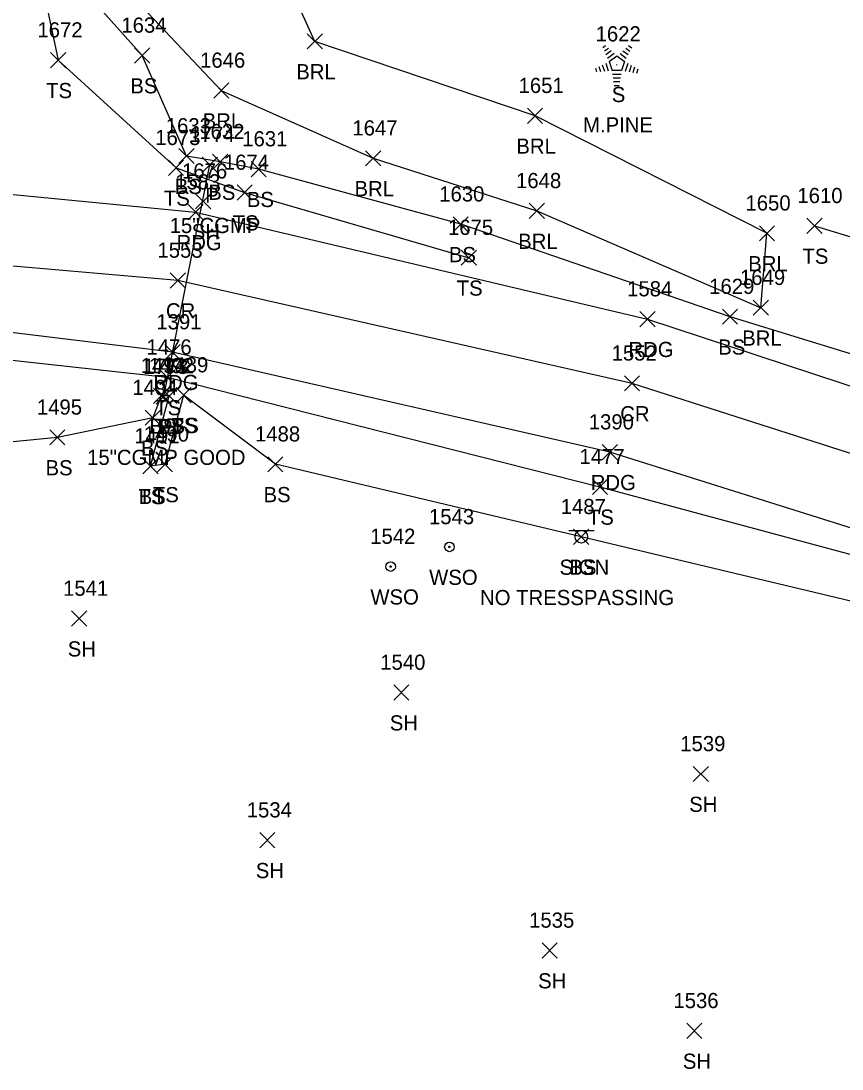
# Model space of a CAD drawing. Extents: x 1609623 to 1616187, y 756677 to 762826.
# Drawn here: x 1610314.5 to 1610422.7, y 761639.6 to 761777.7 of the extents above; entities that cross this region are included whole.
import ezdxf

# ---------------------------------------------------------------- set-up
doc = ezdxf.new("R2010")
doc.units = 0
for name, color, linetype in [('D_A', 7, 'Continuous'), ('D_C', 7, 'Continuous'), ('D_I', 7, 'Continuous'), ('D_TIC', 7, 'Continuous'), ('DCP', 7, 'Continuous'), ('L_A', 7, 'Continuous'), ('L_C', 7, 'Continuous'), ('L_I', 7, 'Continuous'), ('L_TIC', 7, 'Continuous'), ('LABL', 7, 'Continuous'), ('LELB', 7, 'Continuous'), ('LTC', 7, 'Continuous'), ('P_A', 7, 'Continuous'), ('P_I', 7, 'Continuous'), ('P_TIC', 7, 'Continuous'), ('PEU', 7, 'Continuous'), ('PRC', 7, 'Continuous'), ('S_A', 7, 'Continuous'), ('S_C', 7, 'Continuous'), ('S_I', 7, 'Continuous'), ('SSGN', 7, 'Continuous'), ('U_A', 7, 'Continuous'), ('U_I', 7, 'Continuous'), ('UWV', 7, 'Continuous')]:
    doc.layers.add(name, color=color, linetype=linetype)

msp = doc.modelspace()

# ---------------------------------------------------------------- linework, layer by layer
at = {"layer": 'D_TIC'}
for points in [[(1610338.4, 761757.75), (1610340.4, 761759.75)], [(1610340.4, 761757.75), (1610338.4, 761759.75)], [(1610332.32, 761727.19), (1610334.32, 761729.19)], [(1610334.32, 761727.19), (1610332.32, 761729.19)]]:
    msp.add_lwpolyline(points, dxfattribs=at)
at = {"layer": 'DCP'}
msp.add_lwpolyline([(1610333.32, 761728.19), (1610339.4, 761758.75)], dxfattribs=at)
at = {"layer": 'L_TIC'}
for points in [[(1610352.23, 761774.02), (1610354.23, 761776.02)], [(1610354.23, 761774.02), (1610352.23, 761776.02)], [(1610318.42, 761771.53), (1610320.42, 761773.53)], [(1610320.42, 761771.53), (1610318.42, 761773.53)], [(1610329.48, 761772.16), (1610331.48, 761774.16)], [(1610331.48, 761772.16), (1610329.48, 761774.16)], [(1610339.9, 761767.54), (1610341.9, 761769.54)], [(1610341.9, 761767.54), (1610339.9, 761769.54)], [(1610381.23, 761764.21), (1610383.23, 761766.21)], [(1610383.23, 761764.21), (1610381.23, 761766.21)], [(1610335.33, 761758.9), (1610337.33, 761760.9)], [(1610337.33, 761758.9), (1610335.33, 761760.9)], [(1610359.91, 761758.61), (1610361.91, 761760.61)], [(1610361.91, 761758.61), (1610359.91, 761760.61)], [(1610333.94, 761757.35), (1610335.94, 761759.35)], [(1610335.94, 761757.35), (1610333.94, 761759.35)], [(1610339.75, 761758.13), (1610341.75, 761760.13)], [(1610341.75, 761758.13), (1610339.75, 761760.13)], [(1610344.83, 761757.18), (1610346.83, 761759.18)], [(1610346.83, 761757.18), (1610344.83, 761759.18)], [(1610342.98, 761754.09), (1610344.98, 761756.09)], [(1610344.98, 761754.09), (1610342.98, 761756.09)], [(1610337.52, 761752.94), (1610339.52, 761754.94)], [(1610339.52, 761752.94), (1610337.52, 761754.94)], [(1610381.47, 761751.67), (1610383.47, 761753.67)], [(1610383.47, 761751.67), (1610381.47, 761753.67)], [(1610371.44, 761749.91), (1610373.44, 761751.91)], [(1610373.44, 761749.91), (1610371.44, 761751.91)], [(1610418.05, 761749.7), (1610420.05, 761751.7)], [(1610420.05, 761749.7), (1610418.05, 761751.7)], [(1610411.78, 761748.72), (1610413.78, 761750.72)], [(1610413.78, 761748.72), (1610411.78, 761750.72)], [(1610372.5, 761745.5), (1610374.5, 761747.5)], [(1610374.5, 761745.5), (1610372.5, 761747.5)], [(1610410.98, 761738.91), (1610412.98, 761740.91)], [(1610412.98, 761738.91), (1610410.98, 761740.91)], [(1610406.92, 761737.73), (1610408.92, 761739.73)], [(1610408.92, 761737.73), (1610406.92, 761739.73)], [(1610332.79, 761729.74), (1610334.79, 761731.74)], [(1610334.79, 761729.74), (1610332.79, 761731.74)], [(1610331.98, 761727.3), (1610333.98, 761729.3)], [(1610333.98, 761727.3), (1610331.98, 761729.3)], [(1610333.04, 761727.28), (1610335.04, 761729.28)], [(1610335.04, 761727.28), (1610333.04, 761729.28)], [(1610334.94, 761727.39), (1610336.94, 761729.39)], [(1610336.94, 761727.39), (1610334.94, 761729.39)], [(1610334.94, 761727.39), (1610336.94, 761729.39)], [(1610336.94, 761727.39), (1610334.94, 761729.39)], [(1610330.88, 761724.41), (1610332.88, 761726.41)], [(1610332.88, 761724.41), (1610330.88, 761726.41)], [(1610318.31, 761721.82), (1610320.31, 761723.82)], [(1610320.31, 761721.82), (1610318.31, 761723.82)], [(1610330.58, 761718.03), (1610332.58, 761720.03)], [(1610332.58, 761718.03), (1610330.58, 761720.03)], [(1610330.58, 761718.03), (1610332.58, 761720.03)], [(1610332.58, 761718.03), (1610330.58, 761720.03)], [(1610332.48, 761718.27), (1610334.48, 761720.27)], [(1610334.48, 761718.27), (1610332.48, 761720.27)], [(1610347.03, 761718.28), (1610349.03, 761720.28)], [(1610349.03, 761718.28), (1610347.03, 761720.28)], [(1610389.78, 761715.31), (1610391.78, 761717.31)], [(1610391.78, 761715.31), (1610389.78, 761717.31)], [(1610387.31, 761708.71), (1610389.31, 761710.71)], [(1610389.31, 761708.71), (1610387.31, 761710.71)], [(1610321.19, 761697.94), (1610323.19, 761699.94)], [(1610323.19, 761697.94), (1610321.19, 761699.94)], [(1610363.62, 761688.19), (1610365.62, 761690.19)], [(1610365.62, 761688.19), (1610363.62, 761690.19)], [(1610403.06, 761677.46), (1610405.06, 761679.46)], [(1610405.06, 761677.46), (1610403.06, 761679.46)], [(1610345.96, 761668.73), (1610347.96, 761670.73)], [(1610347.96, 761668.73), (1610345.96, 761670.73)], [(1610383.15, 761654.2), (1610385.15, 761656.2)], [(1610385.15, 761654.2), (1610383.15, 761656.2)], [(1610402.21, 761643.6), (1610404.21, 761645.6)], [(1610404.21, 761643.6), (1610402.21, 761645.6)]]:
    msp.add_lwpolyline(points, dxfattribs=at)
at = {"layer": 'LABL'}
msp.add_lwpolyline([(1610330.75, 761800.05), (1610325.36, 761785.05), (1610340.9, 761768.54), (1610360.91, 761759.61), (1610382.47, 761752.67), (1610411.98, 761739.91), (1610412.78, 761749.72), (1610382.23, 761765.21), (1610353.23, 761775.02), (1610345.84, 761791.3)], dxfattribs=at)
at = {"layer": 'LELB'}
for points in [[(1610357.94, 761824.49), (1610329.65, 761813.17), (1610320.02, 761813.81), (1610314.97, 761798.32), (1610316.77, 761785.03), (1610319.42, 761772.53), (1610334.94, 761758.35), (1610343.98, 761755.09), (1610373.5, 761746.5)], [(1610493.54, 761807.83), (1610484.15, 761757.42), (1610484.55, 761721.1), (1610476.31, 761717.56), (1610462.82, 761719), (1610432.23, 761731.26), (1610407.92, 761738.73), (1610372.44, 761750.91), (1610345.83, 761758.18), (1610340.75, 761759.13), (1610336.33, 761759.9), (1610330.48, 761773.16), (1610321.56, 761783.18), (1610327.07, 761799.85), (1610336.71, 761810.65), (1610352.98, 761818.88), (1610362.46, 761822.54)], [(1610419.05, 761750.7), (1610448.86, 761741.64), (1610467.36, 761735.16), (1610472.33, 761756.91), (1610479.31, 761783.98), (1610481.94, 761811.25), (1610453.47, 761810.17), (1610420.45, 761799.24), (1610406.2, 761793.3), (1610384.28, 761797.2), (1610367.96, 761799.15), (1610357.1, 761783.9)], [(1610257.48, 761736.51), (1610289.65, 761735.58), (1610333.79, 761730.74), (1610390.78, 761716.31), (1610438.56, 761703.45), (1610479.41, 761687.45), (1610522.96, 761672.19), (1610559.63, 761661.11), (1610576.64, 761653.22)], [(1610331.58, 761719.03), (1610334.04, 761728.28), (1610332.98, 761728.3), (1610331.88, 761725.41), (1610319.31, 761722.82), (1610270.59, 761718.07), (1610241.74, 761657.34), (1610217.07, 761660.78), (1610191.82, 761655.02), (1610167.15, 761677.06), (1610169.37, 761706.02), (1610154.67, 761706.22), (1610148.61, 761677.65)], [(1610335.94, 761728.39), (1610333.48, 761719.27), (1610331.58, 761719.03)], [(1610558.74, 761658.14), (1610522.76, 761668.49), (1610478.5, 761684.35), (1610437.45, 761698), (1610388.31, 761709.71), (1610348.03, 761719.28), (1610335.94, 761728.39)]]:
    msp.add_lwpolyline(points, dxfattribs=at)
at = {"layer": 'LTC'}
for p, q in [((1610391.15, 761774.22), (1610391.5, 761774.47)), ((1610394.55, 761774.46), (1610394.97, 761774.15)), ((1610391.36, 761773.75), (1610391.89, 761774.13)), ((1610391.57, 761773.28), (1610392.27, 761773.8)), ((1610391.78, 761772.82), (1610392.66, 761773.46)), ((1610392, 761772.36), (1610393.01, 761773.1)), ((1610393.01, 761773.1), (1610394.01, 761772.37)), ((1610393.43, 761773.41), (1610394.24, 761772.82)), ((1610393.81, 761773.76), (1610394.48, 761773.27)), ((1610394.18, 761774.11), (1610394.73, 761773.71)), ((1610390.64, 761771.71), (1610390.85, 761771.06)), ((1610391.09, 761771.93), (1610391.36, 761771.09)), ((1610391.55, 761772.14), (1610391.88, 761771.13)), ((1610392, 761772.36), (1610392.39, 761771.17)), ((1610394.01, 761772.37), (1610393.62, 761771.17)), ((1610394.45, 761772.1), (1610394.11, 761771.06)), ((1610394.89, 761771.85), (1610394.61, 761770.97)), ((1610395.34, 761771.6), (1610395.1, 761770.87)), ((1610390.18, 761771.49), (1610390.33, 761771.03)), ((1610393.62, 761771.17), (1610392.39, 761771.17)), ((1610393.58, 761770.67), (1610392.44, 761770.67)), ((1610395.78, 761771.35), (1610395.6, 761770.78)), ((1610393.5, 761770.17), (1610392.51, 761770.17)), ((1610393.41, 761769.67), (1610392.58, 761769.67)), ((1610393.33, 761769.17), (1610392.66, 761769.17))]:
    msp.add_line(p, q, dxfattribs=at)
at = {"layer": 'P_TIC'}
for points in [[(1610336.52, 761751.5), (1610338.52, 761753.5)], [(1610338.52, 761751.5), (1610336.52, 761753.5)], [(1610334.18, 761742.5), (1610336.18, 761744.5)], [(1610336.18, 761742.5), (1610334.18, 761744.5)], [(1610396.05, 761737.41), (1610398.05, 761739.41)], [(1610398.05, 761737.41), (1610396.05, 761739.41)], [(1610333.48, 761733.06), (1610335.48, 761735.06)], [(1610335.48, 761733.06), (1610333.48, 761735.06)], [(1610394.01, 761728.94), (1610396.01, 761730.94)], [(1610396.01, 761728.94), (1610394.01, 761730.94)], [(1610391.08, 761719.87), (1610393.08, 761721.87)], [(1610393.08, 761719.87), (1610391.08, 761721.87)]]:
    msp.add_lwpolyline(points, dxfattribs=at)
at = {"layer": 'PEU'}
for points in [[(1610292.65, 761756.84), (1610337.52, 761752.5), (1610397.05, 761738.41), (1610444.38, 761722.79), (1610486.74, 761705.69), (1610529.9, 761690.62)], [(1610523.28, 761673.99), (1610480.04, 761689.74), (1610439, 761706.13), (1610392.08, 761720.87), (1610334.48, 761734.06), (1610288.63, 761739.63), (1610237.75, 761740.33), (1610189.36, 761741.54), (1610151.21, 761743.29), (1610095.63, 761747.13), (1610049.42, 761749.13), (1609994.68, 761742.82), (1609943, 761732.03), (1609889.61, 761718.43), (1609806.51, 761697.21)]]:
    msp.add_lwpolyline(points, dxfattribs=at)
at = {"layer": 'PRC'}
msp.add_lwpolyline([(1610601.8, 761670.75), (1610582.15, 761672.46), (1610527.05, 761683.5), (1610483.24, 761698.98), (1610440.53, 761715.33), (1610395.01, 761729.94), (1610335.18, 761743.5), (1610288.69, 761747.54), (1610237.99, 761746.29), (1610189.61, 761747.71), (1610150.7, 761750.53), (1610096.59, 761755.33), (1610048.73, 761756.09), (1609993.41, 761750.2), (1609941.26, 761738.94), (1609887.62, 761725.82), (1609805.01, 761705.08)], dxfattribs=at)
at = {"layer": 'SSGN'}
for p, q in [((1610386.68, 761710.56), (1610390.01, 761710.56)), ((1610388.33, 761709.73), (1610388.33, 761709.73))]:
    msp.add_line(p, q, dxfattribs=at)
msp.add_circle((1610388.33, 761709.73), 0.833, dxfattribs=at)
at = {"layer": 'UWV'}
for centre, radius in [((1610370.95, 761708.38), 0.625), ((1610370.95, 761708.38), 0.0833), ((1610363.21, 761705.79), 0.625), ((1610363.21, 761705.79), 0.0833)]:
    msp.add_circle(centre, radius, dxfattribs=at)

# ---------------------------------------------------------------- texts
at = {"layer": 'D_A'}
for p in [(1610338.78, 761753.75), (1610332.69, 761723.19)]:
    msp.add_text('P', height=2, dxfattribs=at).set_placement(p)
at = {"layer": 'D_C'}
for s, p in [('15"CGMP', (1610334.1, 761749.75)), ('15"CGMP GOOD', (1610323.23, 761719.19))]:
    msp.add_text(s, height=2, dxfattribs=at).set_placement(p)
at = {"layer": 'D_I'}
for s, p in [('1774', (1610336.71, 761761.75)), ('1773', (1610330.62, 761731.19))]:
    msp.add_text(s, height=2, dxfattribs=at).set_placement(p)
at = {"layer": 'L_A'}
for s, p in [('BRL', (1610350.78, 761770.02)), ('TS', (1610317.83, 761767.53)), ('BS', (1610328.92, 761768.16)), ('S', (1610392.34, 761767.01)), ('BRL', (1610338.45, 761763.54)), ('BRL', (1610379.77, 761760.21)), ('BS', (1610334.77, 761754.9)), ('BRL', (1610358.45, 761754.61)), ('TS', (1610333.34, 761753.35)), ('BS', (1610339.19, 761754.13)), ('BS', (1610344.27, 761753.18)), ('SH', (1610337.01, 761748.94)), ('TS', (1610342.39, 761750.09)), ('BRL', (1610380.01, 761747.67)), ('BS', (1610370.88, 761745.91)), ('BRL', (1610410.32, 761744.72)), ('TS', (1610417.46, 761745.7)), ('TS', (1610371.91, 761741.5)), ('BS', (1610406.36, 761733.73)), ('BRL', (1610409.52, 761734.91)), ('TS', (1610332.2, 761725.74)), ('BS', (1610331.42, 761723.3)), ('BS', (1610332.48, 761723.28)), ('TS', (1610334.35, 761723.39)), ('BS', (1610334.38, 761723.39)), ('BS', (1610330.32, 761720.41)), ('BS', (1610317.75, 761717.82)), ('TS', (1610329.99, 761714.03)), ('BS', (1610330.02, 761714.03)), ('TS', (1610331.89, 761714.27)), ('BS', (1610346.47, 761714.28)), ('TS', (1610389.19, 761711.31)), ('BS', (1610386.75, 761704.71)), ('SH', (1610320.68, 761693.94)), ('SH', (1610363.1, 761684.19)), ('SH', (1610402.54, 761673.46)), ('SH', (1610345.45, 761664.73)), ('SH', (1610382.64, 761650.2)), ('SH', (1610401.7, 761639.6))]:
    msp.add_text(s, height=2, dxfattribs=at).set_placement(p)
at = {"layer": 'L_C'}
msp.add_text('M.PINE', height=2, dxfattribs=at).set_placement((1610388.56, 761763.01))
at = {"layer": 'L_I'}
for s, p in [('1672', (1610316.68, 761775.53)), ('1634', (1610327.74, 761776.16)), ('1622', (1610390.21, 761775.01)), ('1646', (1610338.11, 761771.54)), ('1651', (1610380.06, 761768.21)), ('1633', (1610333.59, 761762.9)), ('1673', (1610332.2, 761761.35)), ('1632', (1610338.01, 761762.13)), ('1647', (1610358.17, 761762.61)), ('1631', (1610343.66, 761761.18)), ('1674', (1610341.24, 761758.09)), ('1676', (1610335.73, 761756.94)), ('1648', (1610379.73, 761755.67)), ('1630', (1610369.61, 761753.91)), ('1610', (1610416.79, 761753.7)), ('1650', (1610409.95, 761752.72)), ('1675', (1610370.76, 761749.5)), ('1649', (1610409.23, 761742.91)), ('1629', (1610405.17, 761741.73)), ('1476', (1610331.05, 761733.74)), ('1493', (1610330.29, 761731.3)), ('1492', (1610331.35, 761731.28)), ('1489', (1610333.24, 761731.39)), ('1489', (1610333.24, 761731.39)), ('1494', (1610329.18, 761728.41)), ('1495', (1610316.61, 761725.82)), ('1491', (1610329.45, 761722.03)), ('1491', (1610329.45, 761722.03)), ('1490', (1610330.7, 761722.27)), ('1488', (1610345.34, 761722.28)), ('1477', (1610388.09, 761719.31)), ('1487', (1610385.61, 761712.71)), ('1541', (1610320.06, 761701.94)), ('1540', (1610361.84, 761692.19)), ('1539', (1610401.36, 761681.46)), ('1534', (1610344.26, 761672.73)), ('1535', (1610381.45, 761658.2)), ('1536', (1610400.46, 761647.6))]:
    msp.add_text(s, height=2, dxfattribs=at).set_placement(p)
at = {"layer": 'LTC'}
msp.add_text('.', height=1.04, rotation=270, dxfattribs=at).set_placement((1610392.9, 761772.11))
at = {"layer": 'P_A'}
for s, p in [('RDG', (1610335.01, 761747.5)), ('CR', (1610333.61, 761738.5)), ('RDG', (1610394.54, 761733.41)), ('RDG', (1610331.96, 761729.06)), ('CR', (1610393.45, 761724.94)), ('RDG', (1610389.57, 761715.87))]:
    msp.add_text(s, height=2, dxfattribs=at).set_placement(p)
at = {"layer": 'P_I'}
for s, p in [('1583', (1610334.83, 761755.5)), ('1553', (1610332.49, 761746.5)), ('1584', (1610394.36, 761741.41)), ('1391', (1610332.35, 761737.06)), ('1552', (1610392.32, 761732.94)), ('1390', (1610389.31, 761723.87))]:
    msp.add_text(s, height=2, dxfattribs=at).set_placement(p)
at = {"layer": 'S_A'}
msp.add_text('SIGN', height=2, dxfattribs=at).set_placement((1610385.46, 761704.71))
at = {"layer": 'S_C'}
msp.add_text('NO TRESSPASSING', height=2, dxfattribs=at).set_placement((1610374.99, 761700.71))
at = {"layer": 'S_I'}
msp.add_text('1487', height=2, dxfattribs=at).set_placement((1610385.61, 761712.71))
at = {"layer": 'U_A'}
for p in [(1610368.28, 761703.38), (1610360.54, 761700.79)]:
    msp.add_text('WSO', height=2, dxfattribs=at).set_placement(p)
at = {"layer": 'U_I'}
for s, p in [('1543', (1610368.26, 761711.38)), ('1542', (1610360.52, 761708.79))]:
    msp.add_text(s, height=2, dxfattribs=at).set_placement(p)

doc.saveas('drawing.dxf')
